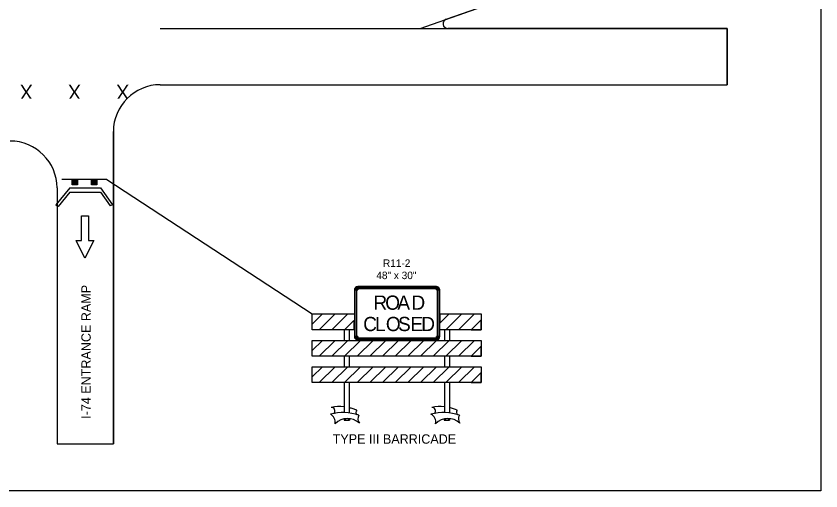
# Model space of a CAD drawing. Extents: x 10133 to 81668, y 7924 to 11018.
# Drawn here: x 11553 to 13268, y 7924 to 8935 of the extents above; entities that cross this region are included whole.
import ezdxf

# ---------------------------------------------------------------- set-up
doc = ezdxf.new("R2010")
doc.units = 0
for name, color, linetype in [('dsnStdBlock', 7, 'Continuous'), ('dsnStdBlockModified', 7, 'Continuous'), ('dsnStdBorder', 7, 'Continuous'), ('dsnstdModifiedBlock', 7, 'Continuous')]:
    doc.layers.add(name, color=color, linetype=linetype)

msp = doc.modelspace()

# ---------------------------------------------------------------- linework, layer by layer
at = {"layer": 'dsnStdBlock'}
for p, q in [((13067.5, 8909.3), (13067.5, 8789.3)), ((11746.4, 8587.3), (11650.2, 8587.3)), ((11672.5, 8586.6), (11683.6, 8586.6)), ((11683.6, 8586.1), (11672.5, 8586.1)), ((11672.5, 8585.5), (11683.6, 8585.5)), ((11683.6, 8585), (11672.5, 8585)), ((11672.5, 8584.6), (11683.6, 8584.6)), ((11683.6, 8584.1), (11672.5, 8584.1)), ((11672.5, 8583.5), (11683.6, 8583.5)), ((11683.6, 8582.9), (11672.5, 8582.9)), ((11672.5, 8582.5), (11683.6, 8582.5)), ((11683.6, 8581.9), (11672.5, 8581.9)), ((11672.5, 8581.1), (11683.6, 8581.1)), ((11683.6, 8580.2), (11672.5, 8580.2)), ((11672.5, 8579.8), (11683.6, 8579.8)), ((11683.6, 8579), (11672.5, 8578.9)), ((11672.5, 8578.5), (11683.6, 8578.5)), ((11683.6, 8577.9), (11672.5, 8577.9)), ((11672.5, 8577.4), (11683.6, 8577.4)), ((11683.6, 8576.8), (11672.5, 8576.8)), ((11713.7, 8586.6), (11724.9, 8586.6)), ((11724.9, 8586.1), (11713.7, 8586.1)), ((11713.7, 8585.5), (11724.9, 8585.5)), ((11724.9, 8585), (11713.7, 8585)), ((11713.7, 8584.6), (11724.9, 8584.6)), ((11724.9, 8584.1), (11713.7, 8584.1)), ((11713.7, 8583.5), (11724.9, 8583.5)), ((11724.9, 8582.9), (11713.7, 8582.9)), ((11713.7, 8582.5), (11724.9, 8582.5)), ((11724.9, 8581.9), (11713.7, 8581.9)), ((11713.7, 8581.1), (11724.9, 8581.1)), ((11724.9, 8580.2), (11713.7, 8580.2)), ((11713.7, 8579.8), (11724.9, 8579.8)), ((11724.9, 8579), (11713.7, 8578.9)), ((11713.7, 8578.5), (11724.9, 8578.5)), ((11724.9, 8577.9), (11713.7, 8577.9)), ((11713.7, 8577.4), (11724.9, 8577.4)), ((11724.9, 8576.8), (11713.7, 8576.8)), ((11746.4, 8587.3), (12183.9, 8300.9)), ((12183.9, 8300.6), (12184.2, 8300.9)), ((12183.9, 8300.1), (12184.7, 8300.9)), ((12251.4, 8267.1), (12251.4, 8244.6)), ((12262.7, 8267.1), (12262.7, 8244.6)), ((12465.2, 8267.1), (12465.2, 8244.6)), ((12476.4, 8267.1), (12476.4, 8244.6)), ((12183.9, 8243.8), (12184.7, 8244.6)), ((12183.9, 8244.4), (12184.2, 8244.6)), ((12251.4, 8210.9), (12251.4, 8188.4)), ((12262.7, 8210.9), (12262.7, 8188.4)), ((12465.2, 8210.9), (12465.2, 8188.4)), ((12476.4, 8210.9), (12476.4, 8188.4)), ((12183.9, 8188.1), (12184.2, 8188.4)), ((12183.9, 8187.6), (12184.7, 8188.4)), ((12251.4, 8154.6), (12251.4, 8090.7)), ((12262.7, 8154.6), (12262.7, 8089.9)), ((12465.2, 8154.6), (12465.2, 8090.7)), ((12476.4, 8154.6), (12476.4, 8090)), ((12251.4, 8077.5), (12251.4, 8074.6)), ((12254.3, 8078), (12254.3, 8074.6)), ((12260, 8078.2), (12260, 8074.6)), ((12262.8, 8078.1), (12262.8, 8074.6)), ((12465.1, 8077.4), (12465.1, 8074.6)), ((12467.9, 8077.4), (12467.9, 8074.6)), ((12473.6, 8078.1), (12473.6, 8074.6)), ((12476.4, 8078.1), (12476.4, 8074.6)), ((12251.4, 8074.6), (12262.8, 8074.6)), ((12465.1, 8074.6), (12476.4, 8074.6)), ((11640, 8024), (11760, 8024))]:
    msp.add_line(p, q, dxfattribs=at)
for points in [[(12469.1, 8928.8), (12755.3, 9029.3), (13067.5, 9029.3), (13067.5, 9149.3), (11860, 9149.3)], [(11860, 8789.3), (13067.5, 8789.3), (13067.5, 8909.3), (12472.4, 8909.3)], [(11640, 8569.3), (11640, 8024), (11760, 8024), (11760, 8689.3)], [(11706.8, 8457.3), (11718.1, 8457.3), (11699.3, 8419.8), (11680.6, 8457.3), (11691.8, 8457.3), (11691.8, 8509.8), (11706.8, 8509.8), (11706.8, 8457.3)], [(12272, 8267.1), (12183.9, 8267.1), (12183.9, 8300.9), (12272, 8300.9)], [(12456.6, 8300.9), (12543.9, 8300.9), (12543.9, 8267.1), (12456.6, 8267.1)]]:
    msp.add_lwpolyline(points, dxfattribs=at)
for points in [[(11672.5, 8587.3), (11683.7, 8587.3), (11683.7, 8576), (11672.5, 8576)], [(11713.7, 8587.3), (11725, 8587.3), (11725, 8576), (11713.7, 8576)], [(12183.9, 8279.5), (12183.9, 8300.9), (12205.3, 8300.9)], [(12198.6, 8267.1), (12232.3, 8300.9), (12259.3, 8300.9), (12225.6, 8267.1)], [(12456.6, 8300.9), (12475.3, 8300.9), (12456.6, 8282.1)], [(12502.3, 8300.9), (12529.3, 8300.9), (12495.6, 8267.1), (12468.6, 8267.1)], [(12252.6, 8267.1), (12272, 8287.1), (12272, 8267.1)], [(12522.6, 8267.1), (12543.9, 8267.1), (12543.9, 8288.5)], [(12183.9, 8223.3), (12183.9, 8244.6), (12205.3, 8244.6)], [(12183.9, 8244.6), (12543.9, 8244.6), (12543.9, 8210.9), (12183.9, 8210.9)], [(12198.6, 8210.9), (12232.3, 8244.6), (12259.3, 8244.6), (12225.6, 8210.9)], [(12286.3, 8244.6), (12313.3, 8244.6), (12279.6, 8210.9), (12252.6, 8210.9)], [(12340.3, 8244.6), (12367.3, 8244.6), (12333.6, 8210.9), (12306.6, 8210.9)], [(12394.3, 8244.6), (12421.3, 8244.6), (12387.6, 8210.9), (12360.6, 8210.9)], [(12448.3, 8244.6), (12475.3, 8244.6), (12441.6, 8210.9), (12414.6, 8210.9)], [(12502.3, 8244.6), (12529.3, 8244.6), (12495.6, 8210.9), (12468.6, 8210.9)], [(12522.6, 8210.9), (12543.9, 8210.9), (12543.9, 8232.3)], [(12183.9, 8188.4), (12543.9, 8188.4), (12543.9, 8154.6), (12183.9, 8154.6)], [(12183.9, 8167), (12183.9, 8188.4), (12205.3, 8188.4)], [(12198.6, 8154.6), (12232.3, 8188.4), (12259.3, 8188.4), (12225.6, 8154.6)], [(12286.3, 8188.4), (12313.3, 8188.4), (12279.6, 8154.6), (12252.6, 8154.6)], [(12340.3, 8188.4), (12367.3, 8188.4), (12333.6, 8154.6), (12306.6, 8154.6)], [(12394.3, 8188.4), (12421.3, 8188.4), (12387.6, 8154.6), (12360.6, 8154.6)], [(12448.3, 8188.4), (12475.3, 8188.4), (12441.6, 8154.6), (12414.6, 8154.6)], [(12502.3, 8188.4), (12529.3, 8188.4), (12495.6, 8154.6), (12468.6, 8154.6)], [(12522.6, 8154.6), (12543.9, 8154.6), (12543.9, 8176)]]:
    msp.add_lwpolyline(points, close=True, dxfattribs=at)
for centre, radius, start, end in [((12472.4, 8919.3), 10, 109.3575, 270), ((12472.4, 8919.3), 10, 109.3575, 270), ((11860, 8689.3), 100, 90, 180), ((11540, 8569.3), 100, 0, 90)]:
    msp.add_arc(centre, radius, start, end, dxfattribs=at)
for centre, major_axis, start_param, end_param in [((12242.3, 8014.4), (0, 89.2), 6.17953, 6.488027), ((12224.7, 8094.1), (0, -7.6), 0.855268, 3.201967), ((12230.5, 7972.3), (0, 132.8), 5.971972, 6.036694), ((12242.3, 8014.4), (0, 89.2), 5.864085, 5.953629), ((12282.7, 8091.6), (0, -6.02), 3.932498, 5.712469), ((12456.5, 8014.4), (0, 89.2), 6.186849, 6.488027), ((12438.9, 8094.1), (0, -7.6), 0.855268, 3.201967), ((12456.5, 8014.4), (0, 89.2), 5.864085, 6.056873), ((12496.9, 8091.6), (0, -6.02), 3.932498, 5.712469), ((12213.9, 8070.6), (0, 18.8), 4.530409, 5.814818), ((12249.5, 7987.2), (0, 103.6), 5.952082, 6.54644), ((12258.9, 8040.4), (0, 37.8), 5.5448, 7.068002), ((12295.3, 8077.6), (0, 14.5), 1.025309, 2.259691), ((12428.2, 8070.6), (0, 18.8), 4.530409, 5.814818), ((12463.8, 7987.2), (0, 103.6), 5.952082, 6.54644), ((12473.1, 8040.4), (0, 37.8), 5.5448, 7.068002), ((12509.6, 8077.6), (0, 14.5), 1.025309, 2.259691)]:
    msp.add_ellipse(centre, major_axis=major_axis, ratio=0.995, start_param=start_param, end_param=end_param, dxfattribs=at)
at = {"layer": 'dsnStdBlockModified'}
for p, q in [((11667.2, 8569.3), (11637.4, 8533.7)), ((11667.2, 8560.1), (11642.1, 8530)), ((11667.2, 8569.3), (11732.8, 8569.3)), ((11667.2, 8560.1), (11732.8, 8560.1)), ((11732.8, 8569.3), (11758.1, 8533.6)), ((11732.8, 8560.1), (11753.5, 8530.9)), ((11637.4, 8533.7), (11642.1, 8530)), ((11758.1, 8533.6), (11753.5, 8530.9))]:
    msp.add_line(p, q, dxfattribs=at)
at = {"layer": 'dsnStdBorder'}
for p, q in [((12273.5, 8352), (12280.6, 8352)), ((12275.3, 8352), (12278.2, 8352)), ((12280.6, 8352), (12280.6, 8359.1)), ((12280.6, 8354.4), (12280.6, 8357.2)), ((12448.2, 8359.1), (12448.2, 8352)), ((12448.2, 8357.2), (12448.2, 8354.4)), ((12448.2, 8352), (12455.3, 8352)), ((12450.5, 8352), (12453.4, 8352)), ((12280.6, 8252.6), (12273.5, 8252.6)), ((12278.2, 8252.6), (12275.3, 8252.6)), ((12280.6, 8245.5), (12280.6, 8252.6)), ((12280.6, 8247.4), (12280.6, 8250.2)), ((12455.3, 8252.6), (12448.2, 8252.6)), ((12448.2, 8252.6), (12448.2, 8245.5)), ((12448.2, 8250.2), (12448.2, 8247.4)), ((12453.4, 8252.6), (12450.5, 8252.6))]:
    msp.add_line(p, q, dxfattribs=at)
for points in [[(12280.6, 8245.5), (12448.2, 8245.5), (12448.2, 8252.6), (12455.3, 8252.6), (12455.3, 8352), (12448.2, 8352), (12448.2, 8359.1), (12280.6, 8359.1), (12280.6, 8352), (12273.5, 8352), (12273.5, 8252.6), (12280.6, 8252.6), (12280.6, 8245.5)], [(12278.2, 8352), (12278.2, 8252.6), (12275.3, 8252.6), (12275.3, 8352), (12278.2, 8352)], [(12448.2, 8354.4), (12280.6, 8354.4), (12280.6, 8357.2), (12448.2, 8357.2), (12448.2, 8354.4)], [(12450.5, 8252.6), (12450.5, 8352), (12453.4, 8352), (12453.4, 8252.6), (12450.5, 8252.6)], [(12280.6, 8250.2), (12448.2, 8250.2), (12448.2, 8247.4), (12280.6, 8247.4), (12280.6, 8250.2)]]:
    msp.add_lwpolyline(points, close=True, dxfattribs=at)
for centre, radius, start, end in [((12280.6, 8352), 7.1, 90.0002, 179.9998), ((12280.6, 8352), 5.21, 90.0002, 179.9998), ((12280.6, 8352), 2.37, 90.0002, 179.9998), ((12448.2, 8352), 7.1, 0, 90.0002), ((12448.2, 8352), 5.21, 0, 90.0002), ((12448.2, 8352), 2.37, 0, 90.0002), ((12280.6, 8252.6), 7.1, 179.9998, 270.0001), ((12280.6, 8252.6), 5.21, 179.9998, 270.0001), ((12280.6, 8252.6), 2.37, 179.9998, 270.0001), ((12448.2, 8252.6), 7.1, 270.0001, 0.0003), ((12448.2, 8252.6), 5.21, 270.0001, 0.0003), ((12448.2, 8252.6), 2.37, 270.0001, 0.0003)]:
    msp.add_arc(centre, radius, start, end, dxfattribs=at)
at = {"layer": 'dsnstdModifiedBlock'}
for p, q in [((12413.8, 8909.3), (12755.3, 9029.3)), ((11860, 8909.3), (13067.5, 8909.3)), ((11860, 8789.3), (13067.5, 8789.3)), ((11760, 8689.3), (11760, 8024)), ((11640, 8569.3), (11640, 8024))]:
    msp.add_line(p, q, dxfattribs=at)
msp.add_lwpolyline([(10132.5, 9944), (13267.5, 9944), (13267.5, 7924), (10132.5, 7924)], close=True, dxfattribs=at)
for centre, start, end in [((11860, 8689.3), 90, 180), ((11540, 8569.3), 0, 90)]:
    msp.add_arc(centre, 100, start, end, dxfattribs=at)

# ---------------------------------------------------------------- texts
at = {"layer": 'dsnStdBlock'}
for s, height, rotation, p in [('X', 30, 180, (11587.9, 8789.3)), ('X', 30, 180, (11690.6, 8789.3)), ('X', 30, 180, (11793.3, 8789.2)), ('I-74 ENTRANCE RAMP', 20, 90, (11711.8, 8077.5))]:
    msp.add_text(s, height=height, rotation=rotation, dxfattribs=at).set_placement(p)
at = {"layer": 'dsnStdBlockModified'}
for s, height, p in [('R11-2', 16, (12334.5, 8401.1)), ('48" x 30"', 16, (12320.3, 8375.1)), ('TYPE III BARRICADE', 20, (12227.3, 8024.5))]:
    msp.add_text(s, height=height, dxfattribs=at).set_placement(p)
at = {"layer": 'dsnStdBorder'}
for s, p in [('R', (12314.2, 8309.9)), ('O', (12339.2, 8309.9)), ('A', (12365.1, 8309.9)), ('D', (12395.1, 8309.9)), ('C', (12292.3, 8264.4)), ('L', (12317.4, 8264.4)), ('O', (12340.6, 8264.4)), ('S', (12366.6, 8264.4)), ('E', (12392.8, 8264.4)), ('D', (12416, 8264.4))]:
    msp.add_text(s, height=30.3, dxfattribs=at).set_placement(p)

doc.saveas('drawing.dxf')
